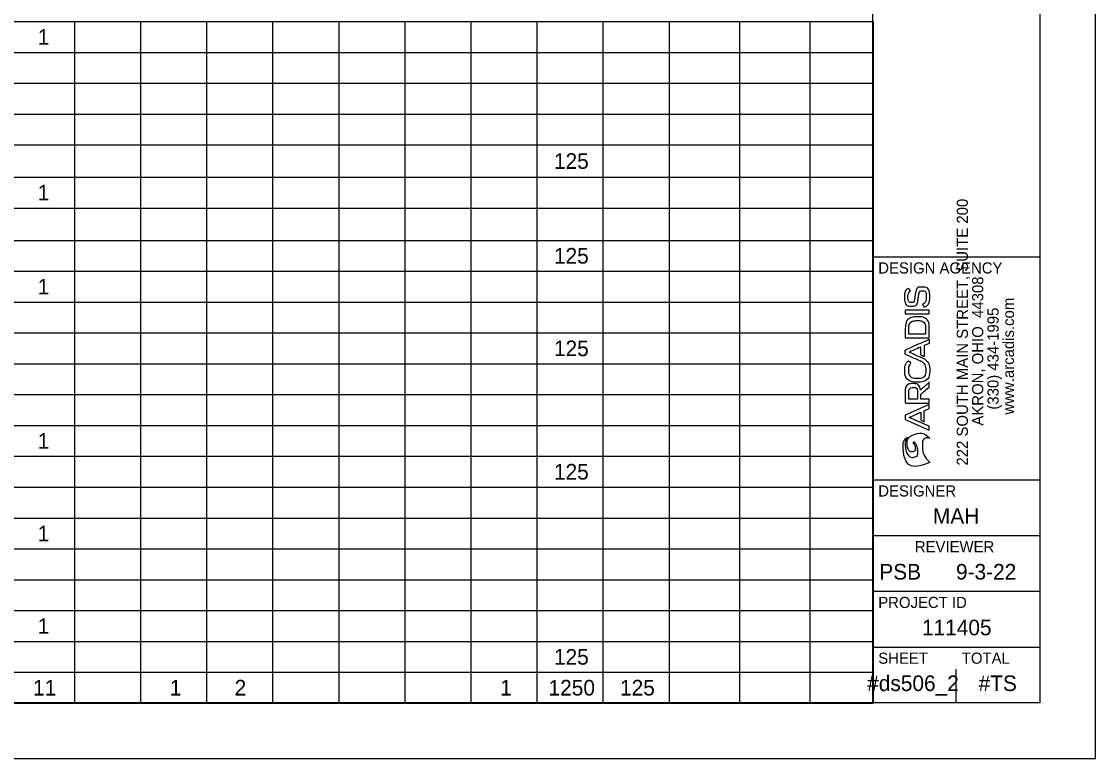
# Model space of a CAD drawing. Extents: x 0.2 to 34.2, y 0 to 22.
# Drawn here: x 24.55 to 34.19, y 0.03 to 6.64 of the extents above; entities that cross this region are included whole.
import ezdxf

# ---------------------------------------------------------------- set-up
doc = ezdxf.new("R2010")
doc.units = 0
for name, color, linetype in [('SH_Border', 7, 'Continuous'), ('SH_Cut_Line', 7, 'Continuous'), ('SH_Data', 7, 'Continuous'), ('SH_Text', 7, 'Continuous')]:
    doc.layers.add(name, color=color, linetype=linetype)

msp = doc.modelspace()

# ---------------------------------------------------------------- linework, layer by layer
at = {"layer": 'SH_Border'}
for p, q in [((32.192, 0.5253), (32.192, 21.5253)), ((32.192, 4.5253), (33.692, 4.5253)), ((32.192, 2.5253), (33.692, 2.5253)), ((32.192, 2.0253), (33.692, 2.0253)), ((32.192, 1.5253), (33.692, 1.5253)), ((32.192, 1.0253), (33.692, 1.0253))]:
    msp.add_line(p, q, dxfattribs=at)
msp.add_lwpolyline([(1.692, 21.5253), (33.692, 21.5253), (33.692, 0.5253), (1.692, 0.5253)], close=True, dxfattribs=at)
at = {"layer": 'SH_Cut_Line'}
msp.add_lwpolyline([(0.192, 0.0253), (34.192, 0.0253), (34.192, 22.0253), (0.192, 22.0253)], close=True, dxfattribs=at)
at = {"layer": 'SH_Data'}
for p, q in [((32.6994, 4.0477), (32.4839, 4.0477)), ((32.4839, 4.0477), (32.4839, 4.0135)), ((32.4839, 4.0135), (32.6994, 4.0135)), ((32.6994, 4.0135), (32.6994, 4.0477)), ((32.942, 3.5253), (32.942, 3.5253)), ((32.942, 3.5253), (32.942, 3.5253)), ((32.6994, 3.2007), (32.4839, 3.1041)), ((32.6994, 3.164), (32.6994, 3.2007)), ((32.4839, 3.1041), (32.4839, 3.0665)), ((32.5202, 3.0853), (32.6227, 3.1303)), ((32.6994, 3.0065), (32.5202, 3.0853)), ((32.6227, 3.1303), (32.6227, 3.0591)), ((32.6541, 3.1441), (32.6994, 3.164)), ((32.6541, 3.0453), (32.6541, 3.1441)), ((32.4839, 3.0665), (32.6994, 2.9699)), ((32.6227, 3.0591), (32.6541, 3.0453)), ((32.6994, 2.9699), (32.6994, 3.0065)), ((32.942, 0.5253), (32.942, 0.8253)), ((32.567, 0.7003), (32.567, 0.7003))]:
    msp.add_line(p, q, dxfattribs=at)
for points, degree in [([(32.5316, 4.2187), (32.5169, 4.2085), (32.5079, 4.1879), (32.5076, 4.1655), (32.5076, 4.1365), (32.5196, 4.1156), (32.5403, 4.1156), (32.5612, 4.1156), (32.567, 4.1396), (32.571, 4.1679), (32.5772, 4.2122), (32.5895, 4.2544), (32.6378, 4.2544), (32.6861, 4.2541), (32.7043, 4.2101), (32.7043, 4.1651), (32.7043, 4.1239), (32.6917, 4.0922), (32.6554, 4.0725), (32.6554, 4.0725), (32.6381, 4.0984), (32.6381, 4.0984), (32.6643, 4.1138), (32.6735, 4.1405), (32.6735, 4.1655), (32.6735, 4.1913), (32.6649, 4.2199), (32.6378, 4.2199), (32.6144, 4.2199), (32.6064, 4.195), (32.6024, 4.1648), (32.5966, 4.1221), (32.5858, 4.0814), (32.5396, 4.0814), (32.495, 4.0811), (32.4778, 4.1258), (32.4778, 4.1645), (32.4778, 4.1956), (32.4852, 4.2267), (32.5141, 4.2449), (32.5141, 4.2449), (32.5316, 4.2187), (32.5316, 4.2187), (32.5316, 4.2187), (32.5316, 4.2187), (32.5316, 4.2187)], 3), ([(32.4839, 3.7975), (32.4839, 3.7975), (32.6994, 3.7975), (32.6994, 3.7975), (32.6994, 3.7975), (32.6994, 3.8791), (32.6994, 3.8791), (32.6994, 3.9545), (32.6443, 3.9884), (32.5898, 3.9871), (32.5366, 3.9862), (32.4839, 3.9526), (32.4839, 3.8791)], 3), ([(32.5169, 3.8317), (32.5169, 3.8317), (32.5169, 3.8791), (32.5169, 3.8791), (32.5169, 3.9299), (32.5532, 3.952), (32.5895, 3.953), (32.6274, 3.9539), (32.6661, 3.9317), (32.6661, 3.8791), (32.6661, 3.8791), (32.6661, 3.8317), (32.6661, 3.8317)], 3), ([(32.4839, 3.8791), (32.4839, 3.8791), (32.4839, 3.7975), (32.4839, 3.7975)], 2), ([(32.4839, 3.689), (32.4839, 3.689), (32.4839, 3.6514), (32.4839, 3.6514), (32.4839, 3.6514), (32.6237, 3.5887), (32.6237, 3.5887), (32.6237, 3.5887), (32.6237, 3.5887), (32.6237, 3.5887), (32.637, 3.582), (32.6454, 3.5746), (32.6482, 3.572), (32.6631, 3.5569), (32.6714, 3.5349), (32.6714, 3.515), (32.6714, 3.4593), (32.6323, 3.4359), (32.5929, 3.4356), (32.5532, 3.4353), (32.5129, 3.4602), (32.5129, 3.515), (32.5129, 3.535), (32.5199, 3.5553), (32.535, 3.5707), (32.535, 3.5707), (32.5129, 3.5938), (32.5129, 3.5938), (32.491, 3.5719), (32.4802, 3.5439), (32.4802, 3.515), (32.4802, 3.438), (32.5366, 3.4011), (32.5932, 3.4014), (32.6498, 3.4017), (32.7037, 3.4368), (32.7037, 3.515), (32.7037, 3.5451), (32.6935, 3.5738), (32.6717, 3.5959), (32.6717, 3.5959), (32.658, 3.6096), (32.6377, 3.6185), (32.6377, 3.6185), (32.6316, 3.6212), (32.6316, 3.6212), (32.6316, 3.6212), (32.6173, 3.6275), (32.6173, 3.6275), (32.6173, 3.6275), (32.6173, 3.6275), (32.6173, 3.6275), (32.6173, 3.6275), (32.5202, 3.6702), (32.5202, 3.6702), (32.5202, 3.6702), (32.6227, 3.7152), (32.6227, 3.7152), (32.6227, 3.7152), (32.6227, 3.644), (32.6227, 3.644), (32.6227, 3.644), (32.6541, 3.6302), (32.6541, 3.6302), (32.6541, 3.6302), (32.6541, 3.729), (32.6541, 3.729), (32.6541, 3.729), (32.6994, 3.7489), (32.6994, 3.7489), (32.6994, 3.7489), (32.6994, 3.7856), (32.6994, 3.7856), (32.6994, 3.7856), (32.4839, 3.689), (32.4839, 3.689), (32.4839, 3.689), (32.4839, 3.689), (32.4839, 3.689)], 3), ([(32.6661, 3.8317), (32.6661, 3.8317), (32.5169, 3.8317), (32.5169, 3.8317)], 2), ([(32.6215, 3.3304), (32.6154, 3.3729), (32.5852, 3.3889), (32.5544, 3.3889), (32.5181, 3.3889), (32.4839, 3.3627), (32.4839, 3.3129), (32.4839, 3.2793), (32.4839, 3.2461), (32.4839, 3.2125), (32.4839, 3.2125), (32.6994, 3.2125), (32.6994, 3.2125), (32.6994, 3.2125), (32.6994, 3.247), (32.6994, 3.247), (32.6994, 3.247), (32.6249, 3.247), (32.6249, 3.247), (32.6249, 3.247), (32.6249, 3.2926), (32.6249, 3.2926), (32.6249, 3.2926), (32.6994, 3.3581), (32.6994, 3.3581), (32.6994, 3.3581), (32.6994, 3.3985), (32.6994, 3.3985)], 3), ([(32.6994, 3.3985), (32.6994, 3.3985), (32.6215, 3.3304), (32.6215, 3.3304)], 2), ([(32.5153, 3.3129), (32.5153, 3.3412), (32.5356, 3.3538), (32.555, 3.3538), (32.5753, 3.3538), (32.5935, 3.3412), (32.5935, 3.3126), (32.5935, 3.3126), (32.5935, 3.247), (32.5935, 3.247), (32.5935, 3.247), (32.5153, 3.247), (32.5153, 3.247)], 3), ([(32.5153, 3.247), (32.5153, 3.247), (32.5153, 3.3129), (32.5153, 3.3129)], 2), ([(32.4643, 2.8118), (32.4736, 2.5998), (32.7062, 2.6811), (32.7062, 2.6811), (32.6862, 2.6996), (32.6383, 2.7591), (32.638, 2.8425), (32.638, 2.8426), (32.638, 2.8427), (32.638, 2.8428), (32.638, 2.883), (32.6722, 2.9067), (32.7062, 2.8976), (32.7062, 2.8976), (32.6328, 2.9602), (32.5492, 2.9254), (32.5214, 2.9138), (32.5006, 2.8826), (32.5006, 2.846), (32.5006, 2.8337), (32.503, 2.8207), (32.5083, 2.8076), (32.5207, 2.7771), (32.5483, 2.773), (32.5611, 2.7792), (32.5705, 2.7838), (32.5751, 2.7929), (32.5751, 2.8027), (32.5751, 2.8043), (32.575, 2.806), (32.5747, 2.8076), (32.5699, 2.8383), (32.5557, 2.8509), (32.5557, 2.858), (32.5557, 2.859), (32.556, 2.8599), (32.5566, 2.8607), (32.5601, 2.8652), (32.5745, 2.8609), (32.5903, 2.8216), (32.5942, 2.8121), (32.5986, 2.7946), (32.5986, 2.7774), (32.5986, 2.7574), (32.5926, 2.7376), (32.5724, 2.731), (32.5348, 2.7187), (32.4898, 2.7629), (32.4846, 2.8293), (32.4843, 2.8327), (32.4841, 2.8372), (32.4841, 2.8404), (32.4841, 2.8742), (32.4993, 2.8984), (32.5094, 2.9104), (32.4863, 2.8967), (32.4651, 2.8677), (32.4643, 2.821), (32.4643, 2.821), (32.4641, 2.8171), (32.4643, 2.8118), (32.4643, 2.8118), (32.4643, 2.8118), (32.4643, 2.8118)], 3)]:
    msp.add_open_spline(points, degree=degree, dxfattribs=at)
at = {"layer": 'SH_Text'}
for p, q in [((24.4346, 6.6359), (32.1955, 6.6359)), ((25.0275, 6.6359), (25.0275, 6.3591)), ((25.6205, 6.6359), (25.6205, 6.3591)), ((26.2134, 6.6359), (26.2134, 6.3591)), ((26.8064, 6.6359), (26.8064, 6.3591)), ((27.3993, 6.6359), (27.3993, 6.3591)), ((27.9922, 6.6359), (27.9922, 6.3591)), ((28.5852, 6.6359), (28.5852, 6.3591)), ((29.1781, 6.6359), (29.1781, 6.3591)), ((29.7711, 6.6359), (29.7711, 6.3591)), ((30.364, 6.6359), (30.364, 6.3591)), ((30.9965, 6.6359), (30.9965, 6.3591)), ((31.629, 6.6359), (31.629, 6.3591)), ((32.1955, 6.6359), (32.1955, 6.3591)), ((24.4346, 6.3591), (32.1955, 6.3591)), ((25.0275, 6.3591), (25.0275, 5.529)), ((25.6205, 6.3591), (25.6205, 5.529)), ((26.2134, 6.3591), (26.2134, 5.529)), ((26.8064, 6.3591), (26.8064, 5.529)), ((27.3993, 6.3591), (27.3993, 5.529)), ((27.9922, 6.3591), (27.9922, 5.529)), ((28.5852, 6.3591), (28.5852, 5.529)), ((29.1781, 6.3591), (29.1781, 5.529)), ((29.7711, 6.3591), (29.7711, 5.529)), ((30.364, 6.3591), (30.364, 5.529)), ((30.9965, 6.3591), (30.9965, 5.529)), ((31.629, 6.3591), (31.629, 5.529)), ((32.1955, 6.3591), (32.1955, 5.529)), ((24.4346, 6.0824), (32.1955, 6.0824)), ((24.4346, 5.8057), (32.1955, 5.8057)), ((24.4346, 5.529), (32.1955, 5.529)), ((25.0275, 5.529), (25.0275, 4.9624)), ((25.6205, 5.529), (25.6205, 4.9624)), ((26.2134, 5.529), (26.2134, 4.9624)), ((26.8064, 5.529), (26.8064, 4.9624)), ((27.3993, 5.529), (27.3993, 4.9624)), ((27.9922, 5.529), (27.9922, 4.9624)), ((28.5852, 5.529), (28.5852, 4.9624)), ((29.1781, 5.529), (29.1781, 4.9624)), ((29.7711, 5.529), (29.7711, 4.9624)), ((30.364, 5.529), (30.364, 4.9624)), ((30.9965, 5.529), (30.9965, 4.9624)), ((31.629, 5.529), (31.629, 4.9624)), ((32.1955, 5.529), (32.1955, 4.9624)), ((24.4346, 5.2391), (32.1955, 5.2391)), ((24.4346, 4.9624), (32.1955, 4.9624)), ((25.0275, 4.9624), (25.0275, 4.6726)), ((25.6205, 4.9624), (25.6205, 4.6726)), ((26.2134, 4.9624), (26.2134, 4.6726)), ((26.8064, 4.9624), (26.8064, 4.6726)), ((27.3993, 4.9624), (27.3993, 4.6726)), ((27.9922, 4.9624), (27.9922, 4.6726)), ((28.5852, 4.9624), (28.5852, 4.6726)), ((29.1781, 4.9624), (29.1781, 4.6726)), ((29.7711, 4.9624), (29.7711, 4.6726)), ((30.364, 4.9624), (30.364, 4.6726)), ((30.9965, 4.9624), (30.9965, 4.6726)), ((31.629, 4.9624), (31.629, 4.6726)), ((32.1955, 4.9624), (32.1955, 4.6726)), ((24.4346, 4.6726), (32.1955, 4.6726)), ((25.0275, 4.6726), (25.0275, 4.3958)), ((25.6205, 4.6726), (25.6205, 4.3958)), ((26.2134, 4.6726), (26.2134, 4.3958)), ((26.8064, 4.6726), (26.8064, 4.3958)), ((27.3993, 4.6726), (27.3993, 4.3958)), ((27.9922, 4.6726), (27.9922, 4.3958)), ((28.5852, 4.6726), (28.5852, 4.3958)), ((29.1781, 4.6726), (29.1781, 4.3958)), ((29.7711, 4.6726), (29.7711, 4.3958)), ((30.364, 4.6726), (30.364, 4.3958)), ((30.9965, 4.6726), (30.9965, 4.3958)), ((31.629, 4.6726), (31.629, 4.3958)), ((32.1955, 4.6726), (32.1955, 4.3958)), ((24.4346, 4.3958), (32.1955, 4.3958)), ((25.0275, 4.3958), (25.0275, 4.1191)), ((25.6205, 4.3958), (25.6205, 4.1191)), ((26.2134, 4.3958), (26.2134, 4.1191)), ((26.8064, 4.3958), (26.8064, 4.1191)), ((27.3993, 4.3958), (27.3993, 4.1191)), ((27.9922, 4.3958), (27.9922, 4.1191)), ((28.5852, 4.3958), (28.5852, 4.1191)), ((29.1781, 4.3958), (29.1781, 4.1191)), ((29.7711, 4.3958), (29.7711, 4.1191)), ((30.364, 4.3958), (30.364, 4.1191)), ((30.9965, 4.3958), (30.9965, 4.1191)), ((31.629, 4.3958), (31.629, 4.1191)), ((32.1955, 4.3958), (32.1955, 4.1191)), ((24.4346, 4.1191), (32.1955, 4.1191)), ((25.0275, 4.1191), (25.0275, 3.8424)), ((25.6205, 4.1191), (25.6205, 3.8424)), ((26.2134, 4.1191), (26.2134, 3.8424)), ((26.8064, 4.1191), (26.8064, 3.8424)), ((27.3993, 4.1191), (27.3993, 3.8424)), ((27.9922, 4.1191), (27.9922, 3.8424)), ((28.5852, 4.1191), (28.5852, 3.8424)), ((29.1781, 4.1191), (29.1781, 3.8424)), ((29.7711, 4.1191), (29.7711, 3.8424)), ((30.364, 4.1191), (30.364, 3.8424)), ((30.9965, 4.1191), (30.9965, 3.8424)), ((31.629, 4.1191), (31.629, 3.8424)), ((32.1955, 4.1191), (32.1955, 3.8424)), ((24.4346, 3.8424), (32.1955, 3.8424)), ((25.0275, 3.8424), (25.0275, 3.289)), ((25.6205, 3.8424), (25.6205, 3.289)), ((26.2134, 3.8424), (26.2134, 3.289)), ((26.8064, 3.8424), (26.8064, 3.289)), ((27.3993, 3.8424), (27.3993, 3.289)), ((27.9922, 3.8424), (27.9922, 3.289)), ((28.5852, 3.8424), (28.5852, 3.289)), ((29.1781, 3.8424), (29.1781, 3.289)), ((29.7711, 3.8424), (29.7711, 3.289)), ((30.364, 3.8424), (30.364, 3.289)), ((30.9965, 3.8424), (30.9965, 3.289)), ((31.629, 3.8424), (31.629, 3.289)), ((32.1955, 3.8424), (32.1955, 3.289)), ((24.4346, 3.5657), (32.1955, 3.5657)), ((24.4346, 3.289), (32.1955, 3.289)), ((25.0275, 3.289), (25.0275, 3.0123)), ((25.6205, 3.289), (25.6205, 3.0123)), ((26.2134, 3.289), (26.2134, 3.0123)), ((26.8064, 3.289), (26.8064, 3.0123)), ((27.3993, 3.289), (27.3993, 3.0123)), ((27.9922, 3.289), (27.9922, 3.0123)), ((28.5852, 3.289), (28.5852, 3.0123)), ((29.1781, 3.289), (29.1781, 3.0123)), ((29.7711, 3.289), (29.7711, 3.0123)), ((30.364, 3.289), (30.364, 3.0123)), ((30.9965, 3.289), (30.9965, 3.0123)), ((31.629, 3.289), (31.629, 3.0123)), ((32.1955, 3.289), (32.1955, 3.0123)), ((24.4346, 3.0123), (32.1955, 3.0123)), ((25.0275, 3.0123), (25.0275, 2.7356)), ((25.6205, 3.0123), (25.6205, 2.7356)), ((26.2134, 3.0123), (26.2134, 2.7356)), ((26.8064, 3.0123), (26.8064, 2.7356)), ((27.3993, 3.0123), (27.3993, 2.7356)), ((27.9922, 3.0123), (27.9922, 2.7356)), ((28.5852, 3.0123), (28.5852, 2.7356)), ((29.1781, 3.0123), (29.1781, 2.7356)), ((29.7711, 3.0123), (29.7711, 2.7356)), ((30.364, 3.0123), (30.364, 2.7356)), ((30.9965, 3.0123), (30.9965, 2.7356)), ((31.629, 3.0123), (31.629, 2.7356)), ((32.1955, 3.0123), (32.1955, 2.7356)), ((24.4346, 2.7356), (32.1955, 2.7356)), ((25.0275, 2.7356), (25.0275, 2.4589)), ((25.6205, 2.7356), (25.6205, 2.4589)), ((26.2134, 2.7356), (26.2134, 2.4589)), ((26.8064, 2.7356), (26.8064, 2.4589)), ((27.3993, 2.7356), (27.3993, 2.4589)), ((27.9922, 2.7356), (27.9922, 2.4589)), ((28.5852, 2.7356), (28.5852, 2.4589)), ((29.1781, 2.7356), (29.1781, 2.4589)), ((29.7711, 2.7356), (29.7711, 2.4589)), ((30.364, 2.7356), (30.364, 2.4589)), ((30.9965, 2.7356), (30.9965, 2.4589)), ((31.629, 2.7356), (31.629, 2.4589)), ((32.1955, 2.7356), (32.1955, 2.4589)), ((24.4346, 2.4589), (32.1955, 2.4589)), ((25.0275, 2.4589), (25.0275, 1.9055)), ((25.6205, 2.4589), (25.6205, 1.9055)), ((26.2134, 2.4589), (26.2134, 1.9055)), ((26.8064, 2.4589), (26.8064, 1.9055)), ((27.3993, 2.4589), (27.3993, 1.9055)), ((27.9922, 2.4589), (27.9922, 1.9055)), ((28.5852, 2.4589), (28.5852, 1.9055)), ((29.1781, 2.4589), (29.1781, 1.9055)), ((29.7711, 2.4589), (29.7711, 1.9055)), ((30.364, 2.4589), (30.364, 1.9055)), ((30.9965, 2.4589), (30.9965, 1.9055)), ((31.629, 2.4589), (31.629, 1.9055)), ((32.1955, 2.4589), (32.1955, 1.9055)), ((24.4346, 2.1822), (32.1955, 2.1822)), ((24.4346, 1.9055), (32.1955, 1.9055)), ((25.0275, 1.9055), (25.0275, 1.6288)), ((25.6205, 1.9055), (25.6205, 1.6288)), ((26.2134, 1.9055), (26.2134, 1.6288)), ((26.8064, 1.9055), (26.8064, 1.6288)), ((27.3993, 1.9055), (27.3993, 1.6288)), ((27.9922, 1.9055), (27.9922, 1.6288)), ((28.5852, 1.9055), (28.5852, 1.6288)), ((29.1781, 1.9055), (29.1781, 1.6288)), ((29.7711, 1.9055), (29.7711, 1.6288)), ((30.364, 1.9055), (30.364, 1.6288)), ((30.9965, 1.9055), (30.9965, 1.6288)), ((31.629, 1.9055), (31.629, 1.6288)), ((32.1955, 1.9055), (32.1955, 1.6288)), ((24.4346, 1.6288), (32.1955, 1.6288)), ((25.0275, 1.6288), (25.0275, 1.3521)), ((25.6205, 1.6288), (25.6205, 1.3521)), ((26.2134, 1.6288), (26.2134, 1.3521)), ((26.8064, 1.6288), (26.8064, 1.3521)), ((27.3993, 1.6288), (27.3993, 1.3521)), ((27.9922, 1.6288), (27.9922, 1.3521)), ((28.5852, 1.6288), (28.5852, 1.3521)), ((29.1781, 1.6288), (29.1781, 1.3521)), ((29.7711, 1.6288), (29.7711, 1.3521)), ((30.364, 1.6288), (30.364, 1.3521)), ((30.9965, 1.6288), (30.9965, 1.3521)), ((31.629, 1.6288), (31.629, 1.3521)), ((32.1955, 1.6288), (32.1955, 1.3521)), ((24.4346, 1.3521), (32.1955, 1.3521)), ((25.0275, 1.3521), (25.0275, 1.0754)), ((25.6205, 1.3521), (25.6205, 1.0754)), ((26.2134, 1.3521), (26.2134, 1.0754)), ((26.8064, 1.3521), (26.8064, 1.0754)), ((27.3993, 1.3521), (27.3993, 1.0754)), ((27.9922, 1.3521), (27.9922, 1.0754)), ((28.5852, 1.3521), (28.5852, 1.0754)), ((29.1781, 1.3521), (29.1781, 1.0754)), ((29.7711, 1.3521), (29.7711, 1.0754)), ((30.364, 1.3521), (30.364, 1.0754)), ((30.9965, 1.3521), (30.9965, 1.0754)), ((31.629, 1.3521), (31.629, 1.0754)), ((32.1955, 1.3521), (32.1955, 1.0754)), ((24.4346, 1.0754), (32.1955, 1.0754)), ((25.0275, 1.0754), (25.0275, 0.522)), ((25.6205, 1.0754), (25.6205, 0.522)), ((26.2134, 1.0754), (26.2134, 0.522)), ((26.8064, 1.0754), (26.8064, 0.522)), ((27.3993, 1.0754), (27.3993, 0.522)), ((27.9922, 1.0754), (27.9922, 0.522)), ((28.5852, 1.0754), (28.5852, 0.522)), ((29.1781, 1.0754), (29.1781, 0.522)), ((29.7711, 1.0754), (29.7711, 0.522)), ((30.364, 1.0754), (30.364, 0.522)), ((30.9965, 1.0754), (30.9965, 0.522)), ((31.629, 1.0754), (31.629, 0.522)), ((32.1955, 1.0754), (32.1955, 0.522)), ((24.4346, 0.7987), (32.1955, 0.7987)), ((24.4346, 0.522), (32.1955, 0.522))]:
    msp.add_line(p, q, dxfattribs=at)

# ---------------------------------------------------------------- texts
at = {"layer": 'SH_Data'}
for s, p in [('222 SOUTH MAIN STREET, SUITE 200', (33.0466, 2.6528)), ('AKRON, OHIO  44308', (33.1844, 3.0109)), ('www.arcadis.com', (33.46, 3.1102)), ('(330) 434-1995', (33.3222, 3.1545))]:
    msp.add_text(s, height=0.1, rotation=90, dxfattribs=at).set_placement(p)
for s, height, p in [('DESIGN AGENCY', 0.1, (32.242, 4.3753)), ('DESIGNER', 0.1, (32.242, 2.3753)), ('MAH', 0.14, (32.7325, 2.1303)), ('REVIEWER', 0.1, (32.5703, 1.8753)), ('PSB', 0.14, (32.2515, 1.6303)), ('9-3-22', 0.14, (32.9396, 1.6303)), ('PROJECT ID', 0.1, (32.242, 1.3753)), ('111405', 0.14, (32.6342, 1.1303)), ('SHEET', 0.1, (32.242, 0.8753)), ('TOTAL', 0.1, (32.992, 0.8753)), ('#ds506_2', 0.14, (32.1427, 0.6303)), ('#TS', 0.14, (33.1427, 0.6303))]:
    msp.add_text(s, height=height, dxfattribs=at).set_placement(p)
at = {"layer": 'SH_Text'}
for s, p in [('1', (24.6983, 6.4275)), ('125', (29.3313, 5.3141)), ('1', (24.6983, 5.0308)), ('125', (29.3313, 4.4642)), ('1', (24.6983, 4.1875)), ('125', (29.3313, 3.6341)), ('1', (24.6983, 2.804)), ('125', (29.3313, 2.5273)), ('1', (24.6983, 1.9738)), ('1', (24.6983, 1.1437)), ('125', (29.3313, 0.867)), ('11', (24.6559, 0.5903)), ('1', (25.8842, 0.5903)), ('2', (26.4656, 0.5903)), ('1', (28.8489, 0.5903)), ('1250', (29.2831, 0.5903)), ('125', (29.9243, 0.5903))]:
    msp.add_text(s, height=0.14, dxfattribs=at).set_placement(p)

doc.saveas('drawing.dxf')
